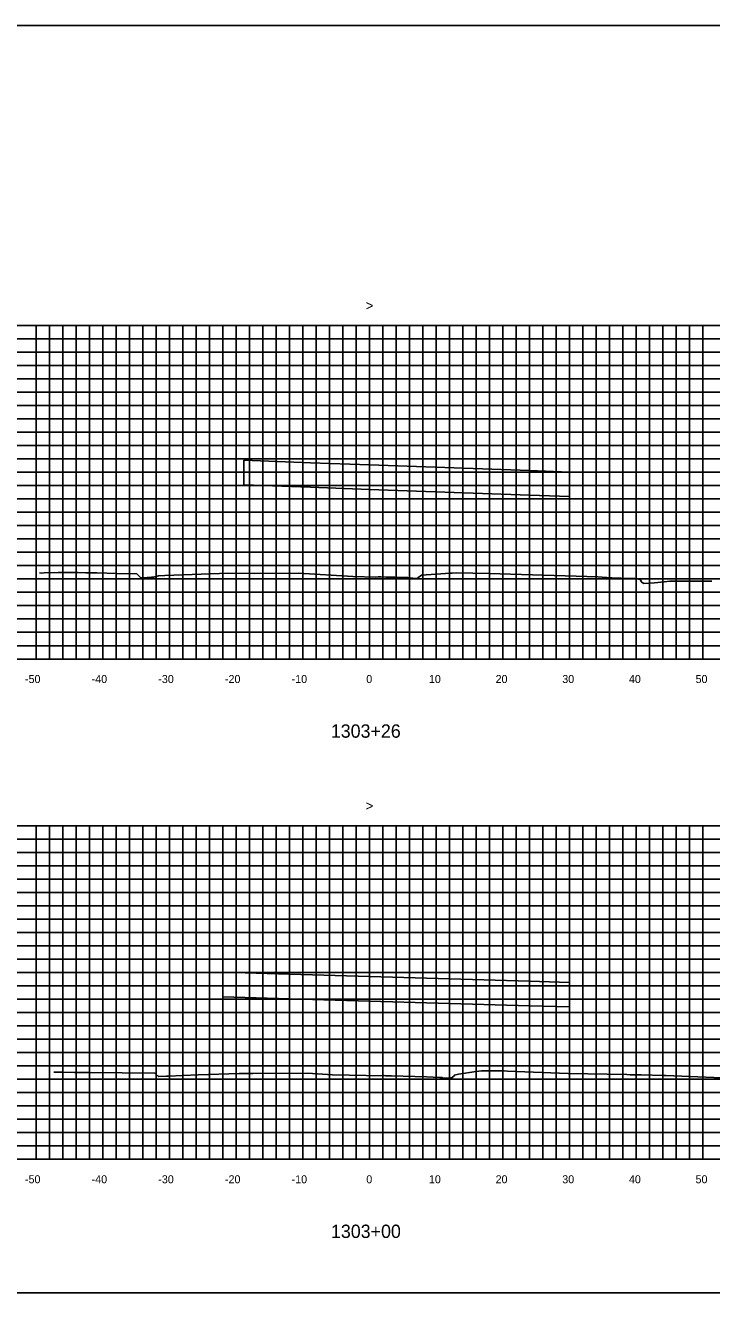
# Model space of a CAD drawing. Extents: x 1797714 to 1804825, y 249015 to 250269.
# Drawn here: x 1803259.4 to 1803362.3, y 250079.4 to 250269.4 of the extents above; entities that cross this region are included whole.
import ezdxf

# ---------------------------------------------------------------- set-up
doc = ezdxf.new("R2010")
doc.units = 0
for name, color, linetype in [('1', 7, 'Continuous'), ('10', 7, 'Continuous'), ('60', 7, 'Continuous'), ('BRG-DECK', 7, 'Continuous'), ('CL-CNST', 7, 'Continuous'), ('Level 62', 7, 'Continuous'), ('M-ROADS', 7, 'Continuous')]:
    doc.layers.add(name, color=color, linetype=linetype)

msp = doc.modelspace()

# ---------------------------------------------------------------- linework, layer by layer
msp.add_lwpolyline([(1803161, 250079.43), (1803461, 250079.43), (1803461, 250269.43), (1803161, 250269.43)], close=True)
at = {"layer": '60'}
for p, q in [((1803161, 250174.43), (1803461, 250174.43)), ((1803261, 250174.37), (1803261, 250174.43)), ((1803271, 250174.37), (1803271, 250174.43)), ((1803281, 250174.37), (1803281, 250174.43)), ((1803291, 250174.37), (1803291, 250174.43)), ((1803301, 250174.37), (1803301, 250174.43)), ((1803311, 250174.37), (1803311, 250174.43)), ((1803321, 250174.37), (1803321, 250174.43)), ((1803331, 250174.37), (1803331, 250174.43)), ((1803341, 250174.37), (1803341, 250174.43)), ((1803351, 250174.37), (1803351, 250174.43)), ((1803361, 250174.37), (1803361, 250174.43)), ((1803161, 250099.43), (1803461, 250099.43)), ((1803261, 250099.37), (1803261, 250099.43)), ((1803271, 250099.37), (1803271, 250099.43)), ((1803281, 250099.37), (1803281, 250099.43)), ((1803291, 250099.37), (1803291, 250099.43)), ((1803301, 250099.37), (1803301, 250099.43)), ((1803311, 250099.37), (1803311, 250099.43)), ((1803321, 250099.37), (1803321, 250099.43)), ((1803331, 250099.37), (1803331, 250099.43)), ((1803341, 250099.37), (1803341, 250099.43)), ((1803351, 250099.37), (1803351, 250099.43)), ((1803361, 250099.37), (1803361, 250099.43))]:
    msp.add_line(p, q, dxfattribs=at)
at = {"layer": 'BRG-DECK'}
for points in [[(1803341, 250198.78), (1803341, 250202.46), (1803335, 250202.68), (1803311, 250203.54), (1803302.13, 250203.86), (1803292.13, 250204.22), (1803292.13, 250200.54), (1803302.13, 250200.18), (1803311, 250199.86), (1803335, 250199)], [(1803341, 250122.26), (1803341, 250125.94), (1803335, 250126.12), (1803311, 250126.83), (1803299, 250127.18), (1803289, 250127.48), (1803289, 250123.8), (1803299, 250123.5), (1803311, 250123.15), (1803335, 250122.44)]]:
    msp.add_lwpolyline(points, close=True, dxfattribs=at)
at = {"layer": 'CL-CNST'}
for points in [[(1803292.13, 250204.22), (1803302.13, 250203.86), (1803311, 250203.54), (1803335, 250202.68), (1803341, 250202.46)], [(1803289, 250127.48), (1803299, 250127.18), (1803311, 250126.83), (1803335, 250126.12), (1803341, 250125.94)]]:
    msp.add_lwpolyline(points, dxfattribs=at)
at = {"layer": 'Level 62'}
for p, q in [((1803161, 250224.43), (1803461, 250224.43)), ((1803261, 250174.43), (1803261, 250224.43)), ((1803263, 250174.43), (1803263, 250224.43)), ((1803265, 250174.43), (1803265, 250224.43)), ((1803267, 250174.43), (1803267, 250224.43)), ((1803269, 250174.43), (1803269, 250224.43)), ((1803271, 250174.43), (1803271, 250224.43)), ((1803273, 250174.43), (1803273, 250224.43)), ((1803275, 250174.43), (1803275, 250224.43)), ((1803277, 250174.43), (1803277, 250224.43)), ((1803279, 250174.43), (1803279, 250224.43)), ((1803281, 250174.43), (1803281, 250224.43)), ((1803283, 250174.43), (1803283, 250224.43)), ((1803285, 250174.43), (1803285, 250224.43)), ((1803287, 250174.43), (1803287, 250224.43)), ((1803289, 250174.43), (1803289, 250224.43)), ((1803291, 250174.43), (1803291, 250224.43)), ((1803293, 250174.43), (1803293, 250224.43)), ((1803295, 250174.43), (1803295, 250224.43)), ((1803297, 250174.43), (1803297, 250224.43)), ((1803299, 250174.43), (1803299, 250224.43)), ((1803301, 250174.43), (1803301, 250224.43)), ((1803303, 250174.43), (1803303, 250224.43)), ((1803305, 250174.43), (1803305, 250224.43)), ((1803307, 250174.43), (1803307, 250224.43)), ((1803309, 250174.43), (1803309, 250224.43)), ((1803311, 250174.43), (1803311, 250224.43)), ((1803313, 250174.43), (1803313, 250224.43)), ((1803315, 250174.43), (1803315, 250224.43)), ((1803317, 250174.43), (1803317, 250224.43)), ((1803319, 250174.43), (1803319, 250224.43)), ((1803321, 250174.43), (1803321, 250224.43)), ((1803323, 250174.43), (1803323, 250224.43)), ((1803325, 250174.43), (1803325, 250224.43)), ((1803327, 250174.43), (1803327, 250224.43)), ((1803329, 250174.43), (1803329, 250224.43)), ((1803331, 250174.43), (1803331, 250224.43)), ((1803333, 250174.43), (1803333, 250224.43)), ((1803335, 250174.43), (1803335, 250224.43)), ((1803337, 250174.43), (1803337, 250224.43)), ((1803339, 250174.43), (1803339, 250224.43)), ((1803341, 250174.43), (1803341, 250224.43)), ((1803343, 250174.43), (1803343, 250224.43)), ((1803345, 250174.43), (1803345, 250224.43)), ((1803347, 250174.43), (1803347, 250224.43)), ((1803349, 250174.43), (1803349, 250224.43)), ((1803351, 250174.43), (1803351, 250224.43)), ((1803353, 250174.43), (1803353, 250224.43)), ((1803355, 250174.43), (1803355, 250224.43)), ((1803357, 250174.43), (1803357, 250224.43)), ((1803359, 250174.43), (1803359, 250224.43)), ((1803361, 250174.43), (1803361, 250224.43)), ((1803161, 250222.43), (1803461, 250222.43)), ((1803161, 250220.43), (1803461, 250220.43)), ((1803161, 250218.43), (1803461, 250218.43)), ((1803161, 250216.43), (1803461, 250216.43)), ((1803161, 250214.43), (1803461, 250214.43)), ((1803161, 250212.43), (1803461, 250212.43)), ((1803161, 250210.43), (1803461, 250210.43)), ((1803161, 250208.43), (1803461, 250208.43)), ((1803161, 250206.43), (1803461, 250206.43)), ((1803161, 250204.43), (1803461, 250204.43)), ((1803161, 250202.43), (1803461, 250202.43)), ((1803161, 250200.43), (1803461, 250200.43)), ((1803161, 250198.43), (1803461, 250198.43)), ((1803161, 250196.43), (1803461, 250196.43)), ((1803161, 250194.43), (1803461, 250194.43)), ((1803161, 250192.43), (1803461, 250192.43)), ((1803161, 250190.43), (1803461, 250190.43)), ((1803161, 250188.43), (1803461, 250188.43)), ((1803161, 250186.43), (1803461, 250186.43)), ((1803161, 250184.43), (1803461, 250184.43)), ((1803161, 250182.43), (1803461, 250182.43)), ((1803161, 250180.43), (1803461, 250180.43)), ((1803161, 250178.43), (1803461, 250178.43)), ((1803161, 250176.43), (1803461, 250176.43)), ((1803161, 250174.43), (1803461, 250174.43)), ((1803161, 250149.43), (1803461, 250149.43)), ((1803261, 250099.43), (1803261, 250149.43)), ((1803263, 250099.43), (1803263, 250149.43)), ((1803265, 250099.43), (1803265, 250149.43)), ((1803267, 250099.43), (1803267, 250149.43)), ((1803269, 250099.43), (1803269, 250149.43)), ((1803271, 250099.43), (1803271, 250149.43)), ((1803273, 250099.43), (1803273, 250149.43)), ((1803275, 250099.43), (1803275, 250149.43)), ((1803277, 250099.43), (1803277, 250149.43)), ((1803279, 250099.43), (1803279, 250149.43)), ((1803281, 250099.43), (1803281, 250149.43)), ((1803283, 250099.43), (1803283, 250149.43)), ((1803285, 250099.43), (1803285, 250149.43)), ((1803287, 250099.43), (1803287, 250149.43)), ((1803289, 250099.43), (1803289, 250149.43)), ((1803291, 250099.43), (1803291, 250149.43)), ((1803293, 250099.43), (1803293, 250149.43)), ((1803295, 250099.43), (1803295, 250149.43)), ((1803297, 250099.43), (1803297, 250149.43)), ((1803299, 250099.43), (1803299, 250149.43)), ((1803301, 250099.43), (1803301, 250149.43)), ((1803303, 250099.43), (1803303, 250149.43)), ((1803305, 250099.43), (1803305, 250149.43)), ((1803307, 250099.43), (1803307, 250149.43)), ((1803309, 250099.43), (1803309, 250149.43)), ((1803311, 250099.43), (1803311, 250149.43)), ((1803313, 250099.43), (1803313, 250149.43)), ((1803315, 250099.43), (1803315, 250149.43)), ((1803317, 250099.43), (1803317, 250149.43)), ((1803319, 250099.43), (1803319, 250149.43)), ((1803321, 250099.43), (1803321, 250149.43)), ((1803323, 250099.43), (1803323, 250149.43)), ((1803325, 250099.43), (1803325, 250149.43)), ((1803327, 250099.43), (1803327, 250149.43)), ((1803329, 250099.43), (1803329, 250149.43)), ((1803331, 250099.43), (1803331, 250149.43)), ((1803333, 250099.43), (1803333, 250149.43)), ((1803335, 250099.43), (1803335, 250149.43)), ((1803337, 250099.43), (1803337, 250149.43)), ((1803339, 250099.43), (1803339, 250149.43)), ((1803341, 250099.43), (1803341, 250149.43)), ((1803343, 250099.43), (1803343, 250149.43)), ((1803345, 250099.43), (1803345, 250149.43)), ((1803347, 250099.43), (1803347, 250149.43)), ((1803349, 250099.43), (1803349, 250149.43)), ((1803351, 250099.43), (1803351, 250149.43)), ((1803353, 250099.43), (1803353, 250149.43)), ((1803355, 250099.43), (1803355, 250149.43)), ((1803357, 250099.43), (1803357, 250149.43)), ((1803359, 250099.43), (1803359, 250149.43)), ((1803361, 250099.43), (1803361, 250149.43)), ((1803161, 250147.43), (1803461, 250147.43)), ((1803161, 250145.43), (1803461, 250145.43)), ((1803161, 250143.43), (1803461, 250143.43)), ((1803161, 250141.43), (1803461, 250141.43)), ((1803161, 250139.43), (1803461, 250139.43)), ((1803161, 250137.43), (1803461, 250137.43)), ((1803161, 250135.43), (1803461, 250135.43)), ((1803161, 250133.43), (1803461, 250133.43)), ((1803161, 250131.43), (1803461, 250131.43)), ((1803161, 250129.43), (1803461, 250129.43)), ((1803161, 250127.43), (1803461, 250127.43)), ((1803161, 250125.43), (1803461, 250125.43)), ((1803161, 250123.43), (1803461, 250123.43)), ((1803161, 250121.43), (1803461, 250121.43)), ((1803161, 250119.43), (1803461, 250119.43)), ((1803161, 250117.43), (1803461, 250117.43)), ((1803161, 250115.43), (1803461, 250115.43)), ((1803161, 250113.43), (1803461, 250113.43)), ((1803161, 250111.43), (1803461, 250111.43)), ((1803161, 250109.43), (1803461, 250109.43)), ((1803161, 250107.43), (1803461, 250107.43)), ((1803161, 250105.43), (1803461, 250105.43)), ((1803161, 250103.43), (1803461, 250103.43)), ((1803161, 250101.43), (1803461, 250101.43)), ((1803161, 250099.43), (1803461, 250099.43))]:
    msp.add_line(p, q, dxfattribs=at)
at = {"layer": 'M-ROADS'}
for points in [[(1803261.47, 250187.37), (1803261.71, 250187.32), (1803262.2, 250187.37), (1803264.29, 250187.42), (1803265.53, 250187.4), (1803266.11, 250187.39), (1803267.3, 250187.38), (1803268.45, 250187.36), (1803270.11, 250187.34), (1803273.08, 250187.27), (1803276.07, 250187.2), (1803276.38, 250186.88), (1803276.67, 250186.6), (1803277.61, 250186.64), (1803278.29, 250186.68), (1803278.6, 250186.71), (1803279.33, 250186.92), (1803280.29, 250186.94), (1803289.84, 250187.3), (1803293.78, 250187.27), (1803300.35, 250187.29), (1803308.47, 250186.78), (1803311.94, 250186.72), (1803312.29, 250186.75), (1803312.69, 250186.73), (1803313.49, 250186.71), (1803314.76, 250186.68), (1803315.88, 250186.65), (1803316.59, 250186.64), (1803316.71, 250186.64), (1803317.82, 250186.51), (1803318.11, 250186.5), (1803318.23, 250186.59), (1803318.8, 250186.98), (1803322.39, 250187.25), (1803322.89, 250187.31), (1803322.98, 250187.31), (1803323.39, 250187.31), (1803324.06, 250187.33), (1803328.88, 250187.26), (1803345.24, 250186.74), (1803347.26, 250186.61), (1803347.32, 250186.61), (1803350.14, 250186.48), (1803350.65, 250186.49), (1803351.05, 250186.48), (1803351.58, 250186.37), (1803351.77, 250186), (1803352.08, 250185.76), (1803353.74, 250185.84), (1803355.18, 250186.01), (1803356.05, 250186.1), (1803359.24, 250186.1), (1803359.45, 250186.1), (1803362.33, 250186.1)], [(1803263.64, 250112.48), (1803264.59, 250112.51), (1803264.87, 250112.49), (1803266.72, 250112.45), (1803266.72, 250112.46), (1803269, 250112.42), (1803278.79, 250112.32), (1803278.88, 250112.22), (1803279.31, 250111.82), (1803280.47, 250111.87), (1803280.78, 250111.9), (1803285.3, 250112.08), (1803291.42, 250112.29), (1803293.47, 250112.31), (1803301.7, 250112.33), (1803305.44, 250112.1), (1803313.02, 250111.96), (1803313.18, 250111.97), (1803313.36, 250111.96), (1803313.73, 250111.96), (1803314.3, 250111.94), (1803319.52, 250111.8), (1803321.54, 250111.69), (1803321.66, 250111.68), (1803321.85, 250111.67), (1803321.91, 250111.65), (1803322.53, 250111.61), (1803322.66, 250111.61), (1803323.03, 250111.61), (1803323.05, 250111.61), (1803323.09, 250111.62), (1803323.16, 250111.57), (1803323.22, 250111.57), (1803323.61, 250111.89), (1803323.63, 250111.9), (1803323.67, 250111.94), (1803323.72, 250112.02), (1803323.72, 250112.05), (1803323.95, 250112.1), (1803324.34, 250112.17), (1803326.96, 250112.57), (1803327.77, 250112.67), (1803328.5, 250112.69), (1803328.6, 250112.69), (1803329.01, 250112.7), (1803331.18, 250112.68), (1803331.69, 250112.66), (1803340.79, 250112.3), (1803349.61, 250112.13), (1803350.11, 250112.11), (1803350.75, 250112.1), (1803350.8, 250112.1), (1803351.29, 250112.1), (1803351.38, 250112.1), (1803351.74, 250112.1), (1803355.07, 250112.01), (1803355.42, 250112), (1803367.43, 250111.49)]]:
    msp.add_lwpolyline(points, dxfattribs=at)

# ---------------------------------------------------------------- texts
at = {"layer": '1'}
for s, p in [('1303+26', (1803305.18, 250162.63)), ('1303+00', (1803305.2, 250087.63))]:
    msp.add_text(s, height=2, dxfattribs=at).set_placement(p)
at = {"layer": '10'}
for s, p in [('-50', (1803259.3, 250170.83)), ('-40', (1803269.3, 250170.83)), ('-30', (1803279.3, 250170.83)), ('-20', (1803289.3, 250170.83)), ('-10', (1803299.3, 250170.83)), ('0', (1803310.5, 250170.83)), ('10', (1803319.9, 250170.83)), ('20', (1803329.9, 250170.83)), ('30', (1803339.9, 250170.83)), ('40', (1803349.9, 250170.83)), ('50', (1803359.9, 250170.83)), ('-50', (1803259.3, 250095.83)), ('-40', (1803269.3, 250095.83)), ('-30', (1803279.3, 250095.83)), ('-20', (1803289.3, 250095.83)), ('-10', (1803299.3, 250095.83)), ('0', (1803310.5, 250095.83)), ('10', (1803319.9, 250095.83)), ('20', (1803329.9, 250095.83)), ('30', (1803339.9, 250095.83)), ('40', (1803349.9, 250095.83)), ('50', (1803359.9, 250095.83))]:
    msp.add_text(s, height=1.2, dxfattribs=at).set_placement(p)
at = {"layer": '60'}
for p in [(1803310.39, 250226.68), (1803310.39, 250151.68)]:
    msp.add_text('>', height=1.5, dxfattribs=at).set_placement(p)

doc.saveas('drawing.dxf')
